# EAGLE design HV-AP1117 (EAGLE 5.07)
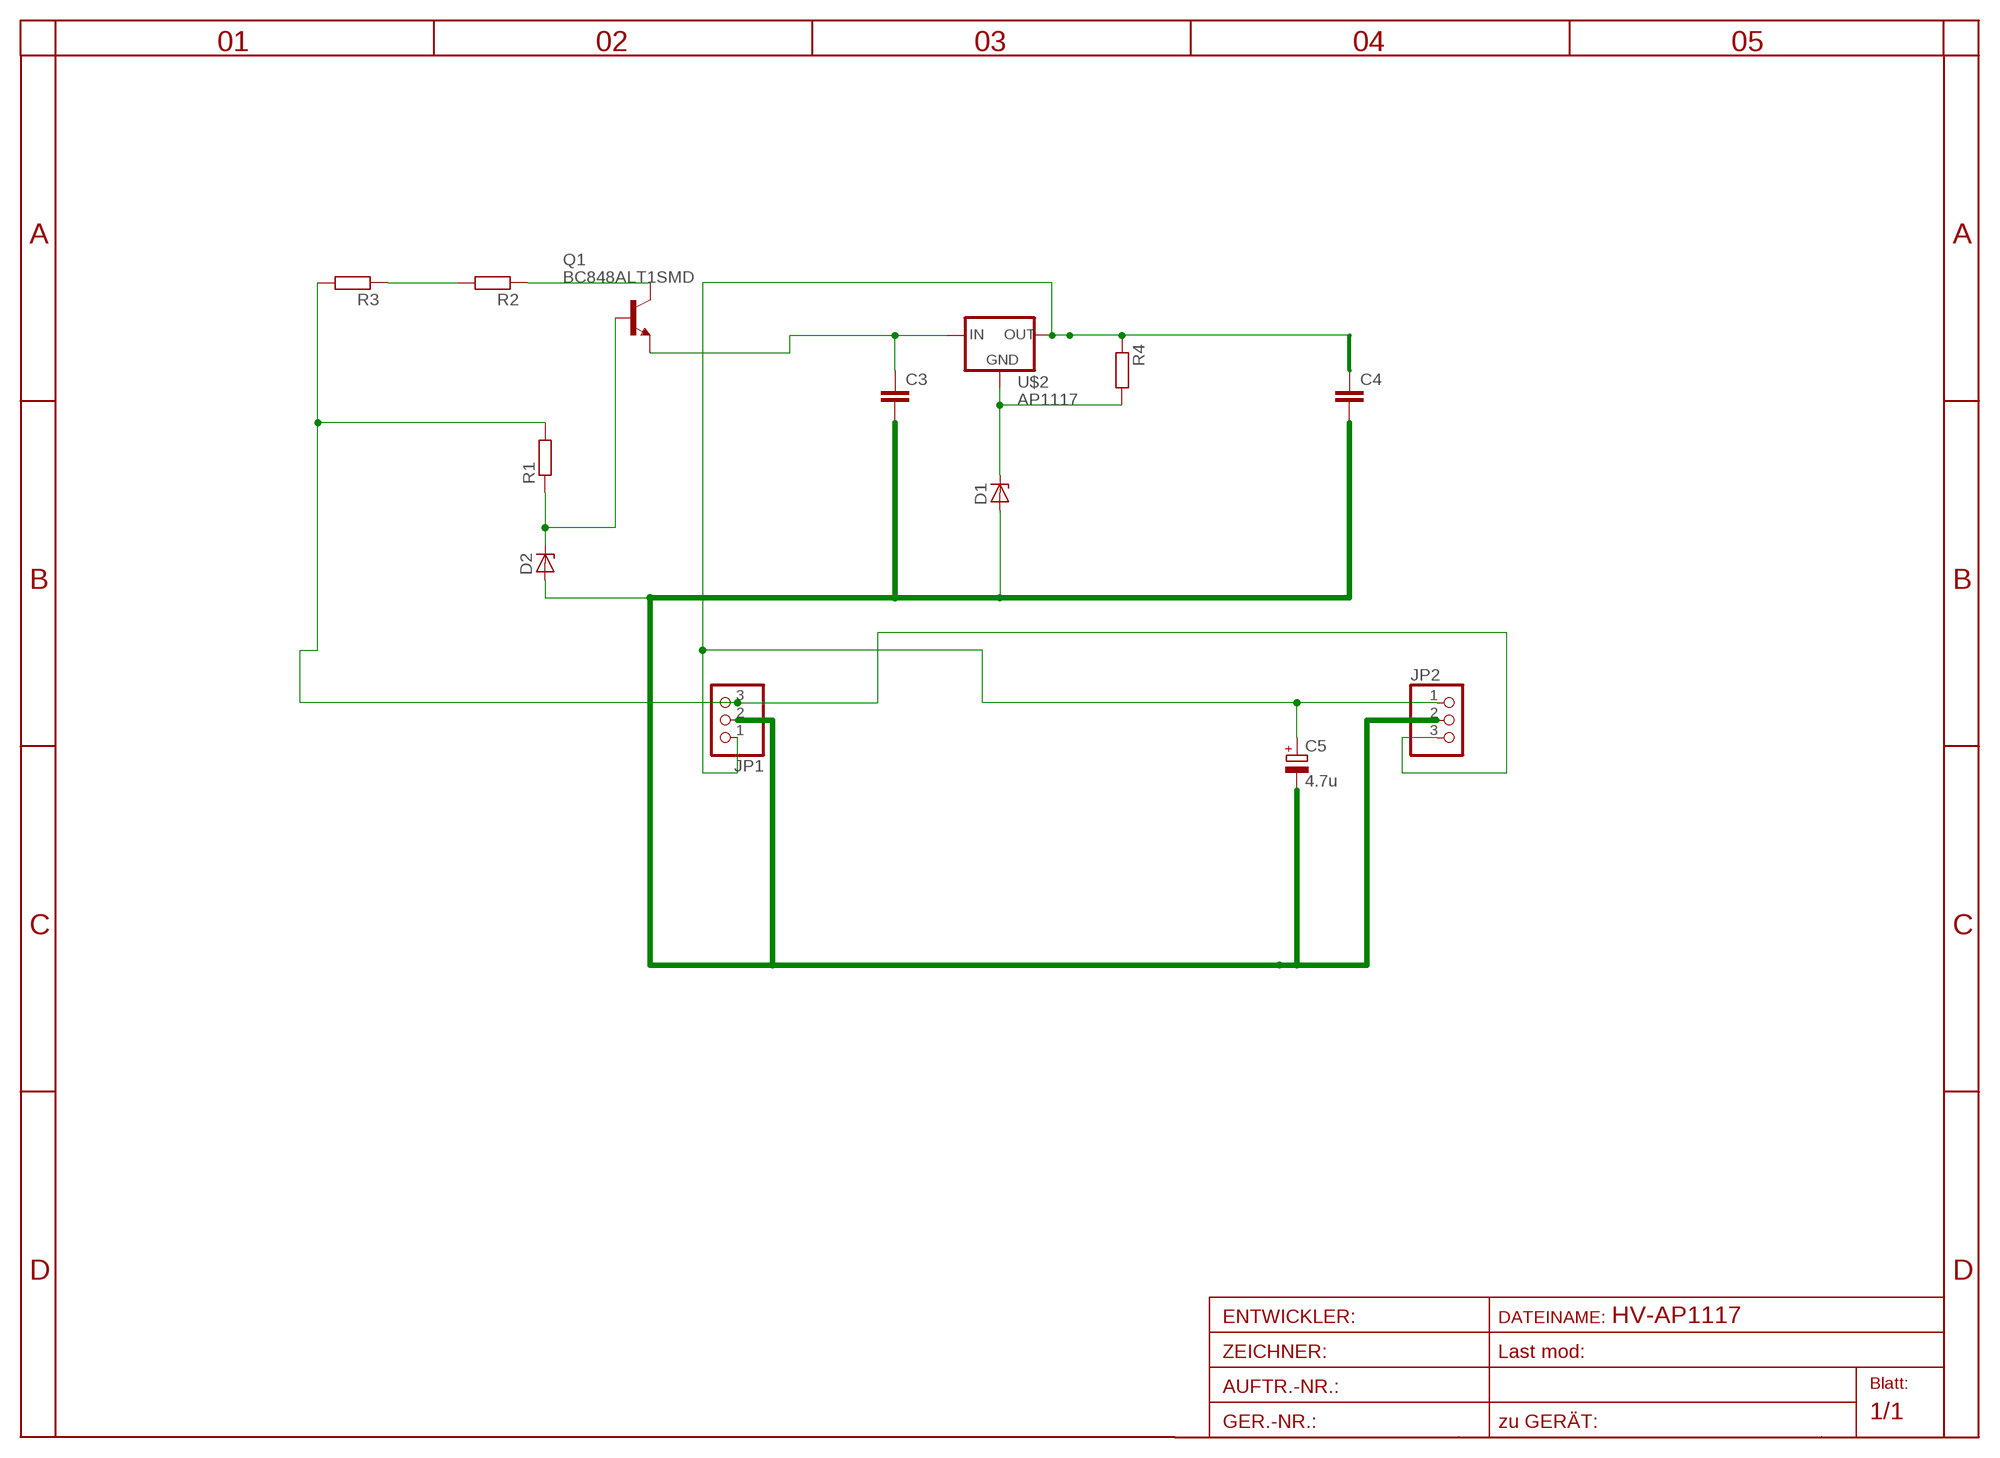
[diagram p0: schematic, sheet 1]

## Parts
C3  C-EUC1206  [C1206]
C4  C-EUC1206  [C1206]
C5  4.7u  CPOL-EUSANYO_SMD_C6  [SANYO-OSCON_SMD_C6]
D1  ZENER-DIODESOD80C  [SOD80C]
D2  ZENER-DIODESOD80C  [SOD80C]
JP1  PINHD-1X3  [1X03]
JP2  PINHD-1X3  [1X03]
Q1  BC848ALT1SMD  [SOT23]
R1  R-EU_R1206  [R1206]
R2  R-EU_R1206  [R1206]
R3  R-EU_R1206  [R1206]
R4  R-EU_R1206  [R1206]
U$2  AP1117  [SOT223]

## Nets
GND: C3.2 C4.2 C5.- D1.A D2.A JP1.2 JP2.2
IN: JP1.3 JP2.3 R1.2 R3.2
N$1: D1.C R4.2 U$2.1(GND)
N$2: C3.1 Q1.2(E) U$2.3(IN)
N$3: R2.2 R3.1
N$4: Q1.3(C) R2.1
N$5: D2.C Q1.1(B) R1.1
OUT: C4.1 C5.+ JP1.1 JP2.1 R4.1 U$2.2(OUT) U$2.4(TAB)

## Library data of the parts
C3 C4 = rcl:C-EU: CAPACITOR, European symbol
C5 = rcl:CPOL-EU: POLARIZED CAPACITOR, European symbol
D1 D2 = diode:ZENER-DIODE: Z-Diode
JP1 JP2 = pinhead:PINHD-1X3: PIN HEADER
Q1 = transistor-npn:BC848*: NPN Transistor
R1-R4 = rcl:R-EU_: RESISTOR, European symbol
U$2 = v-reg:AP1117

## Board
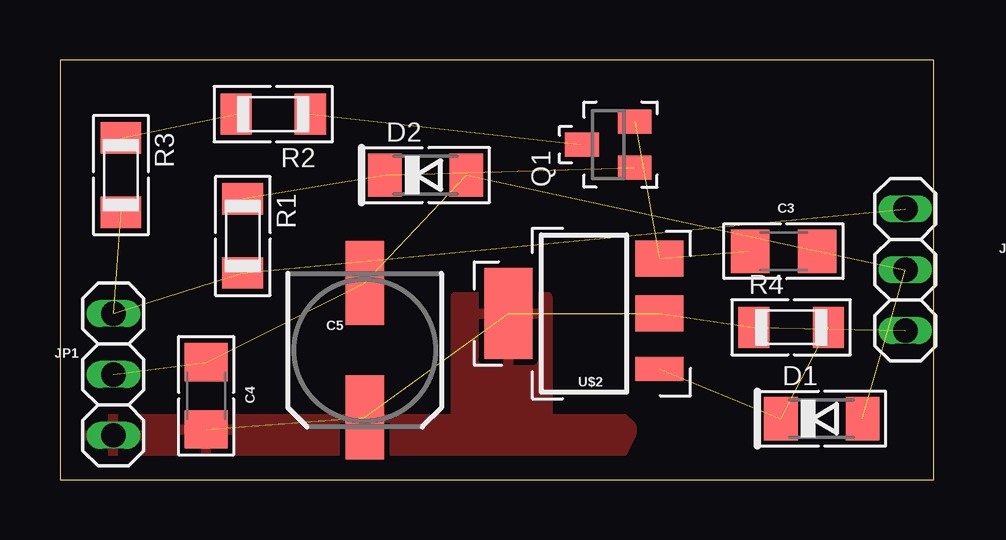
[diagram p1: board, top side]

Size 36.43 x 17.5 mm. Coordinates in mm from the lower left corner, seen from the top.
Outline: 0,0 36.43,0 36.43,17.5 0,17.5 0,0
Copper layers (1*16): Top 0.035mm / dielectric 1.5mm / Bottom 0.035mm
Design rules "default": minimum track width 10mil, minimum drill 20mil, track to track 8mil, track to pad 8mil, pad to pad 8mil, via to via 8mil, smd to smd 8mil, copper to edge 40mil, drill to drill 8mil, minimum pad ring 1mil, minimum via ring 8mil, stop-mask expansion 4mil, vias tented up to drill 0mil, thermal gap 10mil

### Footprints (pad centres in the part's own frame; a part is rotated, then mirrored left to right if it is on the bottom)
C1206 = smd 1.6 x 1.8: 1 -1.4,0; 2 1.4,0
SANYO-OSCON_SMD_C6 = smd 3.5 x 1.6: + 2.8,0; - -2.8,0
SOD80C = smd 1.4 x 1.8: A 1.7,0; C -1.7,0
1X03 = drill 1.016 long: 1 -2.54,0; 2 0,0; 3 2.54,0
SOT23 = smd 1 x 1.4: 1 -0.95,-1.1; 2 0.95,-1.1; 3 0,1.1
R1206 = smd 1.3 x 1.7: 1 -1.55,0; 2 1.55,0
SOT223 = smd 1 x 2: 1 -2.3,-3.15 | smd 1.5 x 2: 2 0,-3.15; 3 2.3,-3.15 | smd 3.8 x 2: 4 0,3.15

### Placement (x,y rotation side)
C3  30.16,9.53 0 top
C4  6.1,3.49 90 top
C5  12.7,5.4 270 top
D1  31.75,2.54 0 top
D2  15.24,12.7 0 top
JP1  2.22,4.38 90 top
JP2  35.24,8.75 90 top
Q1  22.86,13.97 90 top
R1  7.62,10.16 270 top
R2  8.89,15.24 180 top
R3  2.54,12.7 270 top
R4  30.48,6.35 0 top
U$2  21.84,6.92 90 top

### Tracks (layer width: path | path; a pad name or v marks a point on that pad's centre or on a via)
GND  (6 unrouted)
IN  (3 unrouted)
N$1  (2 unrouted)
N$2  (2 unrouted)
N$3  (1 unrouted)
N$4  (1 unrouted)
N$5  (2 unrouted)
OUT  (5 unrouted)
  pour Top (isolate 0.305, rank 2): 0.95,1.59 0.95,2.22 1.27,2.54 23.5,2.54 23.81,2.22 23.81,1.91 23.18,0.64 1.27,0.64
  pour Top: 16.51,7.62 20.32,7.62 20.32,2.54 16.51,2.54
